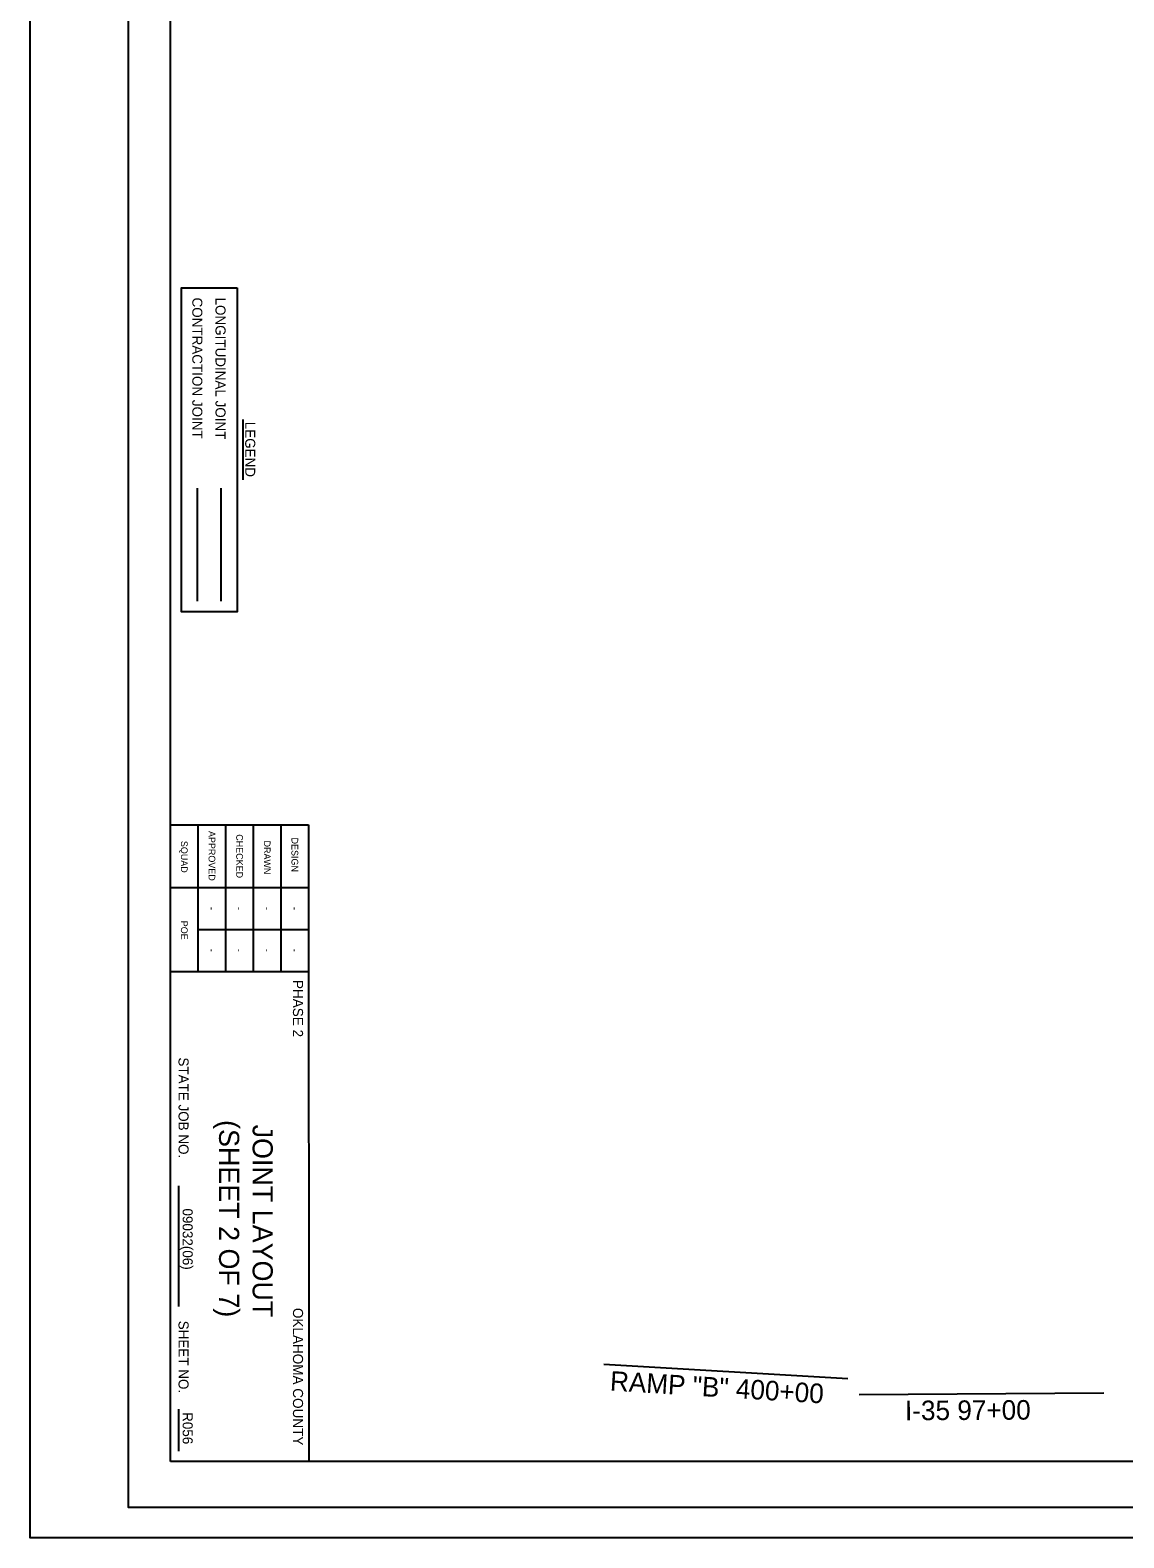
# Model space of a CAD drawing. Extents: x 2150474 to 2151194, y 144668 to 145748.
# Drawn here: x 2150474 to 2150865, y 144668 to 145208 of the extents above; entities that cross this region are included whole.
import ezdxf

# ---------------------------------------------------------------- set-up
doc = ezdxf.new("R2010")
doc.units = 0
for name, color, linetype in [('PR_Joint_Contraction', 7, 'Continuous'), ('PR_Joint_Long', 7, 'Continuous'), ('PR_Txt', 7, 'Continuous'), ('SHT_Match_Lines', 7, 'Continuous'), ('SHT_Plot_Shape_Full', 7, 'Continuous'), ('SHT_Plot_Shape_Half', 7, 'Continuous'), ('SHT_Sheet_Border', 7, 'Continuous'), ('SHT_Standard_Sheet_Lines', 7, 'Continuous'), ('SHT_Standard_Sheet_Txt', 7, 'Continuous')]:
    doc.layers.add(name, color=color, linetype=linetype)

msp = doc.modelspace()

# ---------------------------------------------------------------- linework, layer by layer
at = {"layer": 'PR_Joint_Contraction'}
msp.add_lwpolyline([(2150533.5, 145043.56), (2150533.5, 145003.14)], dxfattribs=at)
at = {"layer": 'PR_Joint_Long'}
msp.add_line((2150541.92, 145043.56), (2150541.92, 145003.14), dxfattribs=at)
at = {"layer": 'PR_Txt'}
msp.add_line((2150549.86, 145068.16), (2150549.86, 145046.56), dxfattribs=at)
msp.add_lwpolyline([(2150547.79, 145115.37), (2150547.79, 144999.35), (2150527.84, 144999.35), (2150527.84, 145115.37)], close=True, dxfattribs=at)
at = {"layer": 'SHT_Match_Lines'}
for p, q in [((2150766.53, 144724.55), (2150679.09, 144729.79)), ((2150858.13, 144719.44), (2150770.53, 144718.92))]:
    msp.add_line(p, q, dxfattribs=at)
at = {"layer": 'SHT_Plot_Shape_Full'}
msp.add_lwpolyline([(2151193.63, 145747.65), (2151193.63, 144667.65), (2150473.63, 144667.65), (2150473.63, 145747.65)], close=True, dxfattribs=at)
at = {"layer": 'SHT_Plot_Shape_Half'}
msp.add_lwpolyline([(2151168.88, 145698.52), (2151168.88, 144678.52), (2150508.88, 144678.52), (2150508.88, 145698.52)], close=True, dxfattribs=at)
at = {"layer": 'SHT_Sheet_Border'}
for p, q in [((2150523.88, 144923.02), (2150573.38, 144923.02)), ((2150573.38, 144923.02), (2150573.39, 144695.02)), ((2150523.88, 144870.53), (2150573.41, 144870.53))]:
    msp.add_line(p, q, dxfattribs=at)
msp.add_lwpolyline([(2150523.88, 144695.02), (2150523.88, 145640.02), (2151153.88, 145640.02), (2151153.88, 144695.02)], close=True, dxfattribs=at)
at = {"layer": 'SHT_Standard_Sheet_Lines'}
for p, q in [((2150523.88, 144900.53), (2150573.41, 144900.53)), ((2150533.79, 144885.53), (2150573.41, 144885.53)), ((2150526.77, 144793.7), (2150526.77, 144750.49)), ((2150526.77, 144713.76), (2150526.77, 144698.69))]:
    msp.add_line(p, q, dxfattribs=at)
for points in [[(2150533.78, 144870.53), (2150533.78, 144923.02)], [(2150543.68, 144870.53), (2150543.68, 144923.02)], [(2150553.58, 144870.53), (2150553.58, 144923.02)], [(2150563.48, 144870.53), (2150563.48, 144923.02)]]:
    msp.add_lwpolyline(points, dxfattribs=at)

# ---------------------------------------------------------------- texts
at = {"layer": 'PR_Txt'}
for s, height, rotation, p in [('CONTRACTION JOINT', 3.6, 270, (2150531.7, 145111.88)), ('LONGITUDINAL JOINT', 3.6, 270, (2150540.01, 145111.88)), ('LEGEND', 3.6, 270, (2150550.65, 145067.39)), ('RAMP "B" 400+00', 7, 356.5283, (2150681.15, 144720.41)), ('I-35 97+00', 7, 0.3078, (2150786.97, 144709.76))]:
    msp.add_text(s, height=height, rotation=rotation, dxfattribs=at).set_placement(p)
at = {"layer": 'SHT_Standard_Sheet_Txt'}
for s, height, p in [('APPROVED', 2.4, (2150537.53, 144920.82)), ('SQUAD', 2.4, (2150527.63, 144917.28)), ('CHECKED', 2.4, (2150547.43, 144919.64)), ('DRAWN', 2.4, (2150557.33, 144917.39)), ('DESIGN', 2.4, (2150567.23, 144918.46)), ('-', 2.4, (2150537.52, 144893.61)), ('-', 2.4, (2150547.42, 144893.61)), ('-', 2.4, (2150557.32, 144893.61)), ('-', 2.4, (2150567.25, 144893.61)), ('POE', 2.4, (2150527.63, 144888.67)), ('-', 2.4, (2150537.52, 144878.61)), ('-', 2.4, (2150547.42, 144878.61)), ('-', 2.4, (2150557.32, 144878.61)), ('-', 2.4, (2150567.25, 144878.61)), ('PHASE 2', 3.621, (2150567.75, 144867.46)), ('STATE JOB NO.', 3.6, (2150526.77, 144839.71)), ('(SHEET 2 OF 7)', 7.2, (2150541.29, 144817.28)), ('JOINT LAYOUT', 7.2, (2150553.31, 144815.65)), ('09032(06)', 3.6, (2150528.25, 144785.62)), ('OKLAHOMA COUNTY', 3.6211, (2150567.75, 144750)), ('SHEET NO. ', 3.6, (2150526.77, 144745.41)), ('R056', 3.6, (2150528.25, 144712.67))]:
    msp.add_text(s, height=height, rotation=270, dxfattribs=at).set_placement(p)

doc.saveas('drawing.dxf')
